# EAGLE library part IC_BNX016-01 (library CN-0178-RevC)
Murata Noise Suppression Filter; P/N BNX016
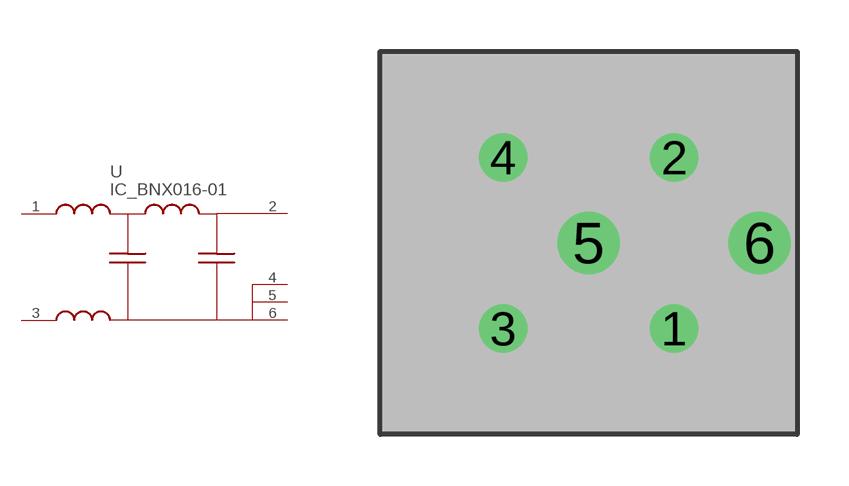
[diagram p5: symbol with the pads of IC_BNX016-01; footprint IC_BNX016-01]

Designator prefix U

## IC_BNX016-01  [IC_BNX016-01]
1  B  pas
2  CB  pas
3  PSG  pas
4  CG  pas
5  CG  pas
6  CG  pas

## Footprint IC_BNX016-01 (pad centres in mm)
Murata BNX016-01 Block Type EMIFIL LC Combined Type
drill 0.914 round: 1 2.5,-2.5; 2 2.5,2.5; 3 -2.5,-2.5; 4 -2.5,2.5
drill 1.219 round: 5 0,0; 6 5,0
